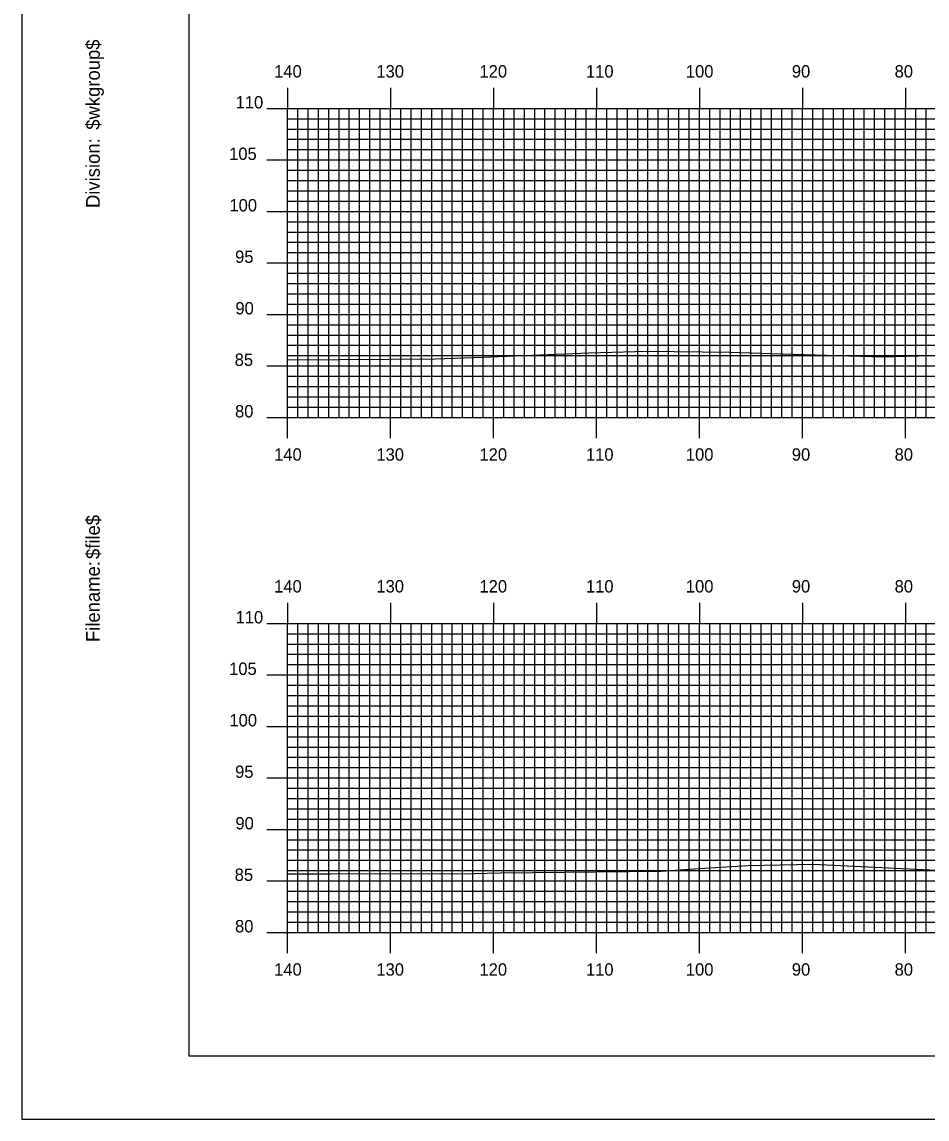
# Model space of a CAD drawing. Extents: x 1762184 to 1762528, y 442591 to 442811.
# Drawn here: x 1762184.5 to 1762272.4, y 442590.5 to 442697.1 of the extents above; entities that cross this region are included whole.
import ezdxf

# ---------------------------------------------------------------- set-up
doc = ezdxf.new("R2010")
doc.units = 0
for name, color, linetype in [('BORDER', 7, 'Continuous'), ('H_V ANNOTATION', 7, 'Continuous'), ('MAJOR', 7, 'Continuous'), ('MINOR', 7, 'Continuous'), ('PLOT BOUNDARY', 7, 'Continuous'), ('S_Roadway_Centerline', 7, 'Continuous')]:
    doc.layers.add(name, color=color, linetype=linetype)

msp = doc.modelspace()

# ---------------------------------------------------------------- linework, layer by layer
at = {"layer": 'BORDER'}
msp.add_lwpolyline([(1762200.67, 442596.67), (1762520.67, 442596.67), (1762520.67, 442806.67), (1762200.67, 442806.67)], close=True, dxfattribs=at)
at = {"layer": 'MAJOR'}
for p, q in [((1762210.27, 442690.67), (1762210.27, 442688.67)), ((1762220.27, 442690.67), (1762220.27, 442688.67)), ((1762230.27, 442690.67), (1762230.27, 442688.67)), ((1762240.27, 442690.67), (1762240.27, 442688.67)), ((1762250.27, 442690.67), (1762250.27, 442688.67)), ((1762260.27, 442690.67), (1762260.27, 442688.67)), ((1762270.27, 442690.67), (1762270.27, 442688.67)), ((1762208.26, 442688.67), (1762210.27, 442688.67)), ((1762210.27, 442688.67), (1762490.27, 442688.67)), ((1762210.27, 442658.67), (1762210.27, 442688.67)), ((1762210.27, 442658.67), (1762210.27, 442688.67)), ((1762210.27, 442688.67), (1762490.27, 442688.67)), ((1762220.27, 442658.67), (1762220.27, 442688.67)), ((1762230.27, 442658.67), (1762230.27, 442688.67)), ((1762240.27, 442658.67), (1762240.27, 442688.67)), ((1762250.27, 442658.67), (1762250.27, 442688.67)), ((1762260.27, 442658.67), (1762260.27, 442688.67)), ((1762270.27, 442658.67), (1762270.27, 442688.67)), ((1762208.26, 442683.67), (1762210.27, 442683.67)), ((1762210.27, 442683.67), (1762490.27, 442683.67)), ((1762208.26, 442678.67), (1762210.27, 442678.67)), ((1762210.27, 442678.67), (1762490.27, 442678.67)), ((1762208.26, 442673.67), (1762210.27, 442673.67)), ((1762210.27, 442673.67), (1762490.27, 442673.67)), ((1762208.26, 442668.67), (1762210.27, 442668.67)), ((1762210.27, 442668.67), (1762490.27, 442668.67)), ((1762208.26, 442663.67), (1762210.27, 442663.67)), ((1762210.27, 442663.67), (1762490.27, 442663.67)), ((1762208.26, 442658.67), (1762210.27, 442658.67)), ((1762210.27, 442658.67), (1762490.27, 442658.67)), ((1762210.27, 442658.67), (1762490.27, 442658.67)), ((1762210.27, 442656.66), (1762210.27, 442658.67)), ((1762220.27, 442656.66), (1762220.27, 442658.67)), ((1762230.27, 442656.66), (1762230.27, 442658.67)), ((1762240.27, 442656.66), (1762240.27, 442658.67)), ((1762250.27, 442656.66), (1762250.27, 442658.67)), ((1762260.27, 442656.66), (1762260.27, 442658.67)), ((1762270.27, 442656.66), (1762270.27, 442658.67)), ((1762210.27, 442640.67), (1762210.27, 442638.67)), ((1762220.27, 442640.67), (1762220.27, 442638.67)), ((1762230.27, 442640.67), (1762230.27, 442638.67)), ((1762240.27, 442640.67), (1762240.27, 442638.67)), ((1762250.27, 442640.67), (1762250.27, 442638.67)), ((1762260.27, 442640.67), (1762260.27, 442638.67)), ((1762270.27, 442640.67), (1762270.27, 442638.67)), ((1762208.26, 442638.67), (1762210.27, 442638.67)), ((1762210.27, 442638.67), (1762490.27, 442638.67)), ((1762210.27, 442608.67), (1762210.27, 442638.67)), ((1762210.27, 442608.67), (1762210.27, 442638.67)), ((1762210.27, 442638.67), (1762490.27, 442638.67)), ((1762220.27, 442608.67), (1762220.27, 442638.67)), ((1762230.27, 442608.67), (1762230.27, 442638.67)), ((1762240.27, 442608.67), (1762240.27, 442638.67)), ((1762250.27, 442608.67), (1762250.27, 442638.67)), ((1762260.27, 442608.67), (1762260.27, 442638.67)), ((1762270.27, 442608.67), (1762270.27, 442638.67)), ((1762208.26, 442633.67), (1762210.27, 442633.67)), ((1762210.27, 442633.67), (1762490.27, 442633.67)), ((1762208.26, 442628.67), (1762210.27, 442628.67)), ((1762210.27, 442628.67), (1762490.27, 442628.67)), ((1762208.26, 442623.67), (1762210.27, 442623.67)), ((1762210.27, 442623.67), (1762490.27, 442623.67)), ((1762208.26, 442618.67), (1762210.27, 442618.67)), ((1762210.27, 442618.67), (1762490.27, 442618.67)), ((1762208.26, 442613.67), (1762210.27, 442613.67)), ((1762210.27, 442613.67), (1762490.27, 442613.67)), ((1762208.26, 442608.67), (1762210.27, 442608.67)), ((1762210.27, 442608.67), (1762490.27, 442608.67)), ((1762210.27, 442608.67), (1762490.27, 442608.67)), ((1762210.27, 442606.66), (1762210.27, 442608.67)), ((1762220.27, 442606.66), (1762220.27, 442608.67)), ((1762230.27, 442606.66), (1762230.27, 442608.67)), ((1762240.27, 442606.66), (1762240.27, 442608.67)), ((1762250.27, 442606.66), (1762250.27, 442608.67)), ((1762260.27, 442606.66), (1762260.27, 442608.67)), ((1762270.27, 442606.66), (1762270.27, 442608.67))]:
    msp.add_line(p, q, dxfattribs=at)
at = {"layer": 'MINOR'}
for p, q in [((1762211.27, 442658.67), (1762211.27, 442688.67)), ((1762212.27, 442658.67), (1762212.27, 442688.67)), ((1762213.27, 442658.67), (1762213.27, 442688.67)), ((1762214.27, 442658.67), (1762214.27, 442688.67)), ((1762215.27, 442658.67), (1762215.27, 442688.67)), ((1762216.27, 442658.67), (1762216.27, 442688.67)), ((1762217.27, 442658.67), (1762217.27, 442688.67)), ((1762218.27, 442658.67), (1762218.27, 442688.67)), ((1762219.27, 442658.67), (1762219.27, 442688.67)), ((1762221.27, 442658.67), (1762221.27, 442688.67)), ((1762222.27, 442658.67), (1762222.27, 442688.67)), ((1762223.27, 442658.67), (1762223.27, 442688.67)), ((1762224.27, 442658.67), (1762224.27, 442688.67)), ((1762225.27, 442658.67), (1762225.27, 442688.67)), ((1762226.27, 442658.67), (1762226.27, 442688.67)), ((1762227.27, 442658.67), (1762227.27, 442688.67)), ((1762228.27, 442658.67), (1762228.27, 442688.67)), ((1762229.27, 442658.67), (1762229.27, 442688.67)), ((1762231.27, 442658.67), (1762231.27, 442688.67)), ((1762232.27, 442658.67), (1762232.27, 442688.67)), ((1762233.27, 442658.67), (1762233.27, 442688.67)), ((1762234.27, 442658.67), (1762234.27, 442688.67)), ((1762235.27, 442658.67), (1762235.27, 442688.67)), ((1762236.27, 442658.67), (1762236.27, 442688.67)), ((1762237.27, 442658.67), (1762237.27, 442688.67)), ((1762238.27, 442658.67), (1762238.27, 442688.67)), ((1762239.27, 442658.67), (1762239.27, 442688.67)), ((1762241.27, 442658.67), (1762241.27, 442688.67)), ((1762242.27, 442658.67), (1762242.27, 442688.67)), ((1762243.27, 442658.67), (1762243.27, 442688.67)), ((1762244.27, 442658.67), (1762244.27, 442688.67)), ((1762245.27, 442658.67), (1762245.27, 442688.67)), ((1762246.27, 442658.67), (1762246.27, 442688.67)), ((1762247.27, 442658.67), (1762247.27, 442688.67)), ((1762248.27, 442658.67), (1762248.27, 442688.67)), ((1762249.27, 442658.67), (1762249.27, 442688.67)), ((1762251.27, 442658.67), (1762251.27, 442688.67)), ((1762252.27, 442658.67), (1762252.27, 442688.67)), ((1762253.27, 442658.67), (1762253.27, 442688.67)), ((1762254.27, 442658.67), (1762254.27, 442688.67)), ((1762255.27, 442658.67), (1762255.27, 442688.67)), ((1762256.27, 442658.67), (1762256.27, 442688.67)), ((1762257.27, 442658.67), (1762257.27, 442688.67)), ((1762258.27, 442658.67), (1762258.27, 442688.67)), ((1762259.27, 442658.67), (1762259.27, 442688.67)), ((1762261.27, 442658.67), (1762261.27, 442688.67)), ((1762262.27, 442658.67), (1762262.27, 442688.67)), ((1762263.27, 442658.67), (1762263.27, 442688.67)), ((1762264.27, 442658.67), (1762264.27, 442688.67)), ((1762265.27, 442658.67), (1762265.27, 442688.67)), ((1762266.27, 442658.67), (1762266.27, 442688.67)), ((1762267.27, 442658.67), (1762267.27, 442688.67)), ((1762268.27, 442658.67), (1762268.27, 442688.67)), ((1762269.27, 442658.67), (1762269.27, 442688.67)), ((1762271.27, 442658.67), (1762271.27, 442688.67)), ((1762272.27, 442658.67), (1762272.27, 442688.67)), ((1762210.27, 442687.67), (1762490.27, 442687.67)), ((1762210.27, 442687.67), (1762212.27, 442687.67)), ((1762210.27, 442686.67), (1762490.27, 442686.67)), ((1762210.27, 442686.67), (1762212.27, 442686.67)), ((1762210.27, 442685.67), (1762490.27, 442685.67)), ((1762210.27, 442685.67), (1762212.27, 442685.67)), ((1762210.27, 442684.67), (1762490.27, 442684.67)), ((1762210.27, 442684.67), (1762212.27, 442684.67)), ((1762210.27, 442682.67), (1762490.27, 442682.67)), ((1762210.27, 442682.67), (1762212.27, 442682.67)), ((1762210.27, 442681.67), (1762490.27, 442681.67)), ((1762210.27, 442681.67), (1762212.27, 442681.67)), ((1762210.27, 442680.67), (1762490.27, 442680.67)), ((1762210.27, 442680.67), (1762212.27, 442680.67)), ((1762210.27, 442679.67), (1762490.27, 442679.67)), ((1762210.27, 442679.67), (1762212.27, 442679.67)), ((1762210.27, 442677.67), (1762490.27, 442677.67)), ((1762210.27, 442677.67), (1762212.27, 442677.67)), ((1762210.27, 442676.67), (1762490.27, 442676.67)), ((1762210.27, 442676.67), (1762212.27, 442676.67)), ((1762210.27, 442675.67), (1762490.27, 442675.67)), ((1762210.27, 442675.67), (1762212.27, 442675.67)), ((1762210.27, 442674.67), (1762490.27, 442674.67)), ((1762210.27, 442674.67), (1762212.27, 442674.67)), ((1762210.27, 442672.67), (1762490.27, 442672.67)), ((1762210.27, 442672.67), (1762212.27, 442672.67)), ((1762210.27, 442671.67), (1762490.27, 442671.67)), ((1762210.27, 442671.67), (1762212.27, 442671.67)), ((1762210.27, 442670.67), (1762490.27, 442670.67)), ((1762210.27, 442670.67), (1762212.27, 442670.67)), ((1762210.27, 442669.67), (1762490.27, 442669.67)), ((1762210.27, 442669.67), (1762212.27, 442669.67)), ((1762210.27, 442667.67), (1762490.27, 442667.67)), ((1762210.27, 442667.67), (1762212.27, 442667.67)), ((1762210.27, 442666.67), (1762490.27, 442666.67)), ((1762210.27, 442666.67), (1762212.27, 442666.67)), ((1762210.27, 442665.67), (1762490.27, 442665.67)), ((1762210.27, 442665.67), (1762212.27, 442665.67)), ((1762210.27, 442664.67), (1762490.27, 442664.67)), ((1762210.27, 442664.67), (1762212.27, 442664.67)), ((1762210.27, 442662.67), (1762490.27, 442662.67)), ((1762210.27, 442662.67), (1762212.27, 442662.67)), ((1762210.27, 442661.67), (1762490.27, 442661.67)), ((1762210.27, 442661.67), (1762212.27, 442661.67)), ((1762210.27, 442660.67), (1762490.27, 442660.67)), ((1762210.27, 442660.67), (1762212.27, 442660.67)), ((1762210.27, 442659.67), (1762490.27, 442659.67)), ((1762210.27, 442659.67), (1762212.27, 442659.67)), ((1762210.27, 442637.67), (1762490.27, 442637.67)), ((1762210.27, 442637.67), (1762212.27, 442637.67)), ((1762211.27, 442608.67), (1762211.27, 442638.67)), ((1762212.27, 442608.67), (1762212.27, 442638.67)), ((1762213.27, 442608.67), (1762213.27, 442638.67)), ((1762214.27, 442608.67), (1762214.27, 442638.67)), ((1762215.27, 442608.67), (1762215.27, 442638.67)), ((1762216.27, 442608.67), (1762216.27, 442638.67)), ((1762217.27, 442608.67), (1762217.27, 442638.67)), ((1762218.27, 442608.67), (1762218.27, 442638.67)), ((1762219.27, 442608.67), (1762219.27, 442638.67)), ((1762221.27, 442608.67), (1762221.27, 442638.67)), ((1762222.27, 442608.67), (1762222.27, 442638.67)), ((1762223.27, 442608.67), (1762223.27, 442638.67)), ((1762224.27, 442608.67), (1762224.27, 442638.67)), ((1762225.27, 442608.67), (1762225.27, 442638.67)), ((1762226.27, 442608.67), (1762226.27, 442638.67)), ((1762227.27, 442608.67), (1762227.27, 442638.67)), ((1762228.27, 442608.67), (1762228.27, 442638.67)), ((1762229.27, 442608.67), (1762229.27, 442638.67)), ((1762231.27, 442608.67), (1762231.27, 442638.67)), ((1762232.27, 442608.67), (1762232.27, 442638.67)), ((1762233.27, 442608.67), (1762233.27, 442638.67)), ((1762234.27, 442608.67), (1762234.27, 442638.67)), ((1762235.27, 442608.67), (1762235.27, 442638.67)), ((1762236.27, 442608.67), (1762236.27, 442638.67)), ((1762237.27, 442608.67), (1762237.27, 442638.67)), ((1762238.27, 442608.67), (1762238.27, 442638.67)), ((1762239.27, 442608.67), (1762239.27, 442638.67)), ((1762241.27, 442608.67), (1762241.27, 442638.67)), ((1762242.27, 442608.67), (1762242.27, 442638.67)), ((1762243.27, 442608.67), (1762243.27, 442638.67)), ((1762244.27, 442608.67), (1762244.27, 442638.67)), ((1762245.27, 442608.67), (1762245.27, 442638.67)), ((1762246.27, 442608.67), (1762246.27, 442638.67)), ((1762247.27, 442608.67), (1762247.27, 442638.67)), ((1762248.27, 442608.67), (1762248.27, 442638.67)), ((1762249.27, 442608.67), (1762249.27, 442638.67)), ((1762251.27, 442608.67), (1762251.27, 442638.67)), ((1762252.27, 442608.67), (1762252.27, 442638.67)), ((1762253.27, 442608.67), (1762253.27, 442638.67)), ((1762254.27, 442608.67), (1762254.27, 442638.67)), ((1762255.27, 442608.67), (1762255.27, 442638.67)), ((1762256.27, 442608.67), (1762256.27, 442638.67)), ((1762257.27, 442608.67), (1762257.27, 442638.67)), ((1762258.27, 442608.67), (1762258.27, 442638.67)), ((1762259.27, 442608.67), (1762259.27, 442638.67)), ((1762261.27, 442608.67), (1762261.27, 442638.67)), ((1762262.27, 442608.67), (1762262.27, 442638.67)), ((1762263.27, 442608.67), (1762263.27, 442638.67)), ((1762264.27, 442608.67), (1762264.27, 442638.67)), ((1762265.27, 442608.67), (1762265.27, 442638.67)), ((1762266.27, 442608.67), (1762266.27, 442638.67)), ((1762267.27, 442608.67), (1762267.27, 442638.67)), ((1762268.27, 442608.67), (1762268.27, 442638.67)), ((1762269.27, 442608.67), (1762269.27, 442638.67)), ((1762271.27, 442608.67), (1762271.27, 442638.67)), ((1762272.27, 442608.67), (1762272.27, 442638.67)), ((1762210.27, 442636.67), (1762490.27, 442636.67)), ((1762210.27, 442636.67), (1762212.27, 442636.67)), ((1762210.27, 442635.67), (1762490.27, 442635.67)), ((1762210.27, 442635.67), (1762212.27, 442635.67)), ((1762210.27, 442634.67), (1762490.27, 442634.67)), ((1762210.27, 442634.67), (1762212.27, 442634.67)), ((1762210.27, 442632.67), (1762490.27, 442632.67)), ((1762210.27, 442632.67), (1762212.27, 442632.67)), ((1762210.27, 442631.67), (1762490.27, 442631.67)), ((1762210.27, 442631.67), (1762212.27, 442631.67)), ((1762210.27, 442630.67), (1762490.27, 442630.67)), ((1762210.27, 442630.67), (1762212.27, 442630.67)), ((1762210.27, 442629.67), (1762490.27, 442629.67)), ((1762210.27, 442629.67), (1762212.27, 442629.67)), ((1762210.27, 442627.67), (1762490.27, 442627.67)), ((1762210.27, 442627.67), (1762212.27, 442627.67)), ((1762210.27, 442626.67), (1762490.27, 442626.67)), ((1762210.27, 442626.67), (1762212.27, 442626.67)), ((1762210.27, 442625.67), (1762490.27, 442625.67)), ((1762210.27, 442625.67), (1762212.27, 442625.67)), ((1762210.27, 442624.67), (1762490.27, 442624.67)), ((1762210.27, 442624.67), (1762212.27, 442624.67)), ((1762210.27, 442622.67), (1762490.27, 442622.67)), ((1762210.27, 442622.67), (1762212.27, 442622.67)), ((1762210.27, 442621.67), (1762490.27, 442621.67)), ((1762210.27, 442621.67), (1762212.27, 442621.67)), ((1762210.27, 442620.67), (1762490.27, 442620.67)), ((1762210.27, 442620.67), (1762212.27, 442620.67)), ((1762210.27, 442619.67), (1762490.27, 442619.67)), ((1762210.27, 442619.67), (1762212.27, 442619.67)), ((1762210.27, 442617.67), (1762490.27, 442617.67)), ((1762210.27, 442617.67), (1762212.27, 442617.67)), ((1762210.27, 442616.67), (1762490.27, 442616.67)), ((1762210.27, 442616.67), (1762212.27, 442616.67)), ((1762210.27, 442615.67), (1762490.27, 442615.67)), ((1762210.27, 442615.67), (1762212.27, 442615.67)), ((1762210.27, 442614.67), (1762490.27, 442614.67)), ((1762210.27, 442614.67), (1762212.27, 442614.67)), ((1762210.27, 442612.67), (1762490.27, 442612.67)), ((1762210.27, 442612.67), (1762212.27, 442612.67)), ((1762210.27, 442611.67), (1762490.27, 442611.67)), ((1762210.27, 442611.67), (1762212.27, 442611.67)), ((1762210.27, 442610.67), (1762490.27, 442610.67)), ((1762210.27, 442610.67), (1762212.27, 442610.67)), ((1762210.27, 442609.67), (1762490.27, 442609.67)), ((1762210.27, 442609.67), (1762212.27, 442609.67))]:
    msp.add_line(p, q, dxfattribs=at)
at = {"layer": 'PLOT BOUNDARY'}
msp.add_lwpolyline([(1762184.48, 442590.55), (1762524.48, 442590.55), (1762524.48, 442810.55), (1762184.48, 442810.55)], close=True, dxfattribs=at)
at = {"layer": 'S_Roadway_Centerline'}
for points in [[(1762210.27, 442664.26), (1762220.11, 442664.32), (1762224.62, 442664.36), (1762228.4, 442664.49), (1762239.57, 442664.93), (1762245.09, 442665.09), (1762253.28, 442665.02), (1762259.34, 442664.82), (1762268.09, 442664.55), (1762279.62, 442664.87)], [(1762210.27, 442614.35), (1762214.49, 442614.34), (1762225.1, 442614.39), (1762227.17, 442614.37), (1762230.91, 442614.45), (1762246.57, 442614.63), (1762249.76, 442614.83), (1762254.96, 442615.16), (1762261.27, 442615.28), (1762274.65, 442614.64)]]:
    msp.add_lwpolyline(points, dxfattribs=at)

# ---------------------------------------------------------------- texts
at = {"layer": 'BORDER'}
for s, p in [('$wkgroup$', (1762192.04, 442686.6)), ('Division:', (1762192.04, 442679)), ('$file$', (1762192.04, 442644.92)), ('Filename:', (1762192.04, 442636.86))]:
    msp.add_text(s, height=1.339, rotation=90, dxfattribs=at).set_placement(p)
at = {"layer": 'H_V ANNOTATION'}
for s, p in [('140', (1762208.97, 442691.67)), ('130', (1762218.9, 442691.67)), ('120', (1762228.91, 442691.67)), ('110', (1762239.25, 442691.67)), ('100', (1762248.95, 442691.67)), ('90', (1762259.24, 442691.67)), ('80', (1762269.22, 442691.67)), ('110', (1762205.23, 442688.67)), ('105', (1762204.6, 442683.67)), ('100', (1762204.63, 442678.67)), ('95', (1762205.18, 442673.67)), ('90', (1762205.21, 442668.67)), ('85', (1762205.14, 442663.67)), ('80', (1762205.17, 442658.67)), ('140', (1762208.97, 442654.47)), ('130', (1762218.9, 442654.47)), ('120', (1762228.91, 442654.47)), ('110', (1762239.25, 442654.47)), ('100', (1762248.95, 442654.47)), ('90', (1762259.24, 442654.47)), ('80', (1762269.22, 442654.47)), ('140', (1762208.97, 442641.67)), ('130', (1762218.9, 442641.67)), ('120', (1762228.91, 442641.67)), ('110', (1762239.25, 442641.67)), ('100', (1762248.95, 442641.67)), ('90', (1762259.24, 442641.67)), ('80', (1762269.22, 442641.67)), ('110', (1762205.23, 442638.67)), ('105', (1762204.6, 442633.67)), ('100', (1762204.63, 442628.67)), ('95', (1762205.18, 442623.67)), ('90', (1762205.21, 442618.67)), ('85', (1762205.14, 442613.67)), ('80', (1762205.17, 442608.67)), ('140', (1762208.97, 442604.47)), ('130', (1762218.9, 442604.47)), ('120', (1762228.91, 442604.47)), ('110', (1762239.25, 442604.47)), ('100', (1762248.95, 442604.47)), ('90', (1762259.24, 442604.47)), ('80', (1762269.22, 442604.47))]:
    msp.add_text(s, height=1.2, dxfattribs=at).set_placement(p)
at = {"layer": 'MAJOR'}
for p in [(1762210.26, 442658.67), (1762210.26, 442608.67)]:
    msp.add_text('-', height=0.012, dxfattribs=at).set_placement(p)

doc.saveas('drawing.dxf')
